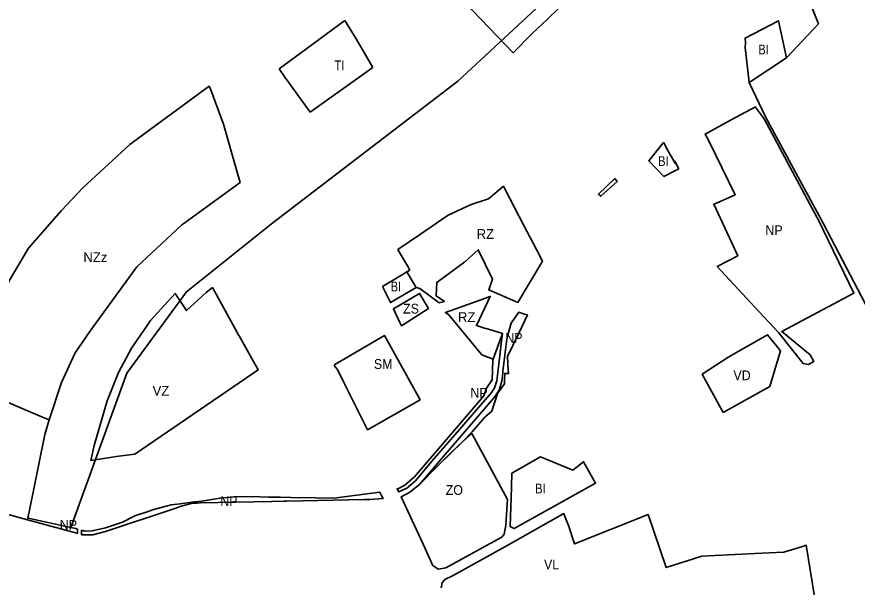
# Model space of a CAD drawing. Extents: x -650276 to -642489, y -1074311 to -1066658.
# Drawn here: x -647227 to -646196, y -1073124 to -1072424 of the extents above; entities that cross this region are included whole.
import ezdxf

# ---------------------------------------------------------------- set-up
doc = ezdxf.new("R2010")
doc.units = 0
doc.header["$LTSCALE"] = 4.8
for name, color, linetype, lineweight in [('18', 7, 'Continuous', 35), ('2', 7, 'Continuous', 35), ('30', 7, 'Continuous', 35), ('34', 7, 'Continuous', 35), ('35', 7, 'Continuous', 35), ('36', 7, 'Continuous', 35), ('41', 7, 'Continuous', 35), ('42', 7, 'Continuous', 35), ('46', 7, 'Continuous', 35), ('48', 7, 'Continuous', 35), ('54', 7, 'Continuous', 35), ('6', 7, 'Continuous', 35)]:
    doc.layers.add(name, color=color, linetype=linetype, lineweight=lineweight)
doc.layers.add('62', color=7, linetype='Continuous')
doc.layers.add('63', color=7, linetype='Continuous')

msp = doc.modelspace()

# ---------------------------------------------------------------- linework, layer by layer
at = {"layer": '18'}
msp.add_lwpolyline([(-646837.81, -1072851.3), (-646836.5, -1072853.76), (-646833.67, -1072857.15), (-646824.89, -1072874.66), (-646796.68, -1072930.92), (-646732.28, -1072894.29), (-646775.85, -1072815.39), (-646834.08, -1072849.15)], close=True, dxfattribs=at)
at = {"layer": '2'}
msp.add_line((-646417.787, -1072612.168), (-646414.77, -1072610.61), dxfattribs=at)
for points in [[(-646333.34, -1072461.67), (-646328.45, -1072504.81), (-646282.47, -1072474.34), (-646292.44, -1072428.89), (-646333.33, -1072450.12), (-646332.68, -1072456.19)], [(-646778.2, -1072755.19), (-646755.1, -1072741.28), (-646748.3, -1072737.01), (-646737.05, -1072756.4), (-646768.74, -1072774.78)], [(-646620.38, -1073015.9), (-646620.71, -1073025.49), (-646621.44, -1073049.79), (-646616.55, -1073052.21), (-646516.7, -1072996.65), (-646531.46, -1072970.12), (-646544.68, -1072980.62), (-646584.23, -1072964.22), (-646619.48, -1072984.34)]]:
    msp.add_lwpolyline(points, close=True, dxfattribs=at)
for points in [[(-646420.36, -1072601.78), (-646427.95, -1072588.07), (-646432.57, -1072579.75), (-646433.36, -1072578.45), (-646451.458, -1072601.008), (-646433.024, -1072620.04), (-646417.787, -1072612.168)], [(-646414.77, -1072610.61), (-646419.11, -1072602.03), (-646419.47, -1072601.31), (-646419.02, -1072604.18), (-646420.36, -1072601.78)]]:
    msp.add_lwpolyline(points, dxfattribs=at)
at = {"layer": '30'}
for points in [[(-646824.42, -1072428.58), (-646878.91, -1072468.54), (-646905.18, -1072487.8)], [(-646867.283, -1072540.984), (-646791.569, -1072487.198), (-646790.354, -1072486.136), (-646810.77, -1072451.09), (-646824.42, -1072428.58)], [(-646905.18, -1072487.8), (-646898.1, -1072498.02), (-646893.64, -1072504.45), (-646867.283, -1072540.984)]]:
    msp.add_lwpolyline(points, dxfattribs=at)
at = {"layer": '34'}
msp.add_lwpolyline([(-646247.76, -1073138.19), (-646258.14, -1073072.71), (-646262.94, -1073074.15), (-646285.77, -1073081.01), (-646312.87, -1073082.4), (-646386.27, -1073086.15), (-646430.02, -1073100.1), (-646452.08, -1073034.96), (-646542.62, -1073071.1), (-646550.01, -1073048.55), (-646552.79, -1073041.53), (-646555.79, -1073033.92), (-646624.69, -1073072.66), (-646691.76, -1073109.71), (-646701.78, -1073114.9), (-646704.98, -1073119), (-646706.23, -1073125.02)], dxfattribs=at)
at = {"layer": '35'}
msp.add_lwpolyline([(-646360.22, -1072909.57), (-646303.02, -1072877.74), (-646289.63, -1072834.04), (-646305.56, -1072814.43), (-646353.25, -1072841.63), (-646385.86, -1072862.59)], close=True, dxfattribs=at)
at = {"layer": '36'}
for points in [[(-646987.154, -1072756.377), (-646995.02, -1072762.45), (-647005.249, -1072771.938), (-647019.06, -1072784.57), (-647032.7, -1072763.68), (-647050.492, -1072782.771)], [(-646954.7, -1072815.232), (-646957.105, -1072810.92), (-646987.154, -1072756.377)], [(-647050.492, -1072782.771), (-647063.04, -1072796.74), (-647067.22, -1072802.77), (-647086.65, -1072830.76), (-647102.38, -1072860.7), (-647116.33, -1072895.3)], [(-647136.39, -1072968.63), (-647110.32, -1072964.56), (-647107.01, -1072964.04), (-647105.4, -1072963.84), (-647082.36, -1072960.95), (-646931.1, -1072857.55), (-646954.51, -1072815.63), (-646954.7, -1072815.232)], [(-647116.33, -1072895.3), (-647132.47, -1072950.4), (-647136.39, -1072968.63)]]:
    msp.add_lwpolyline(points, dxfattribs=at)
at = {"layer": '41'}
msp.add_lwpolyline([(-646756.92, -1072799.26), (-646754.96, -1072803.29), (-646722.072, -1072782.236), (-646732.76, -1072763.81), (-646765, -1072782.52)], close=True, dxfattribs=at)
at = {"layer": '42'}
msp.add_lwpolyline([(-646696.83, -1072385.81), (-646618.158, -1072468.098), (-646594.606, -1072444.422), (-646575.792, -1072426.789), (-646504.244, -1072357.026)], dxfattribs=at)
msp.add_lwpolyline([(-646668.53, -1072935.52), (-646680.07, -1072945.74), (-646710.3, -1072975.31), (-646732.95, -1072998.07), (-646744.92, -1073007.46), (-646755.58, -1073013.43), (-646728.25, -1073071.54), (-646719.09, -1073092.43), (-646716.98, -1073097.26), (-646709.88, -1073101.87), (-646700.42, -1073100.42), (-646650.54, -1073072.96), (-646631.82, -1073062.65), (-646629.15, -1073059.18), (-646626.91, -1073048.17), (-646626.55, -1073041.48), (-646625.01, -1073016.38)], close=True, dxfattribs=at)
at = {"layer": '46'}
msp.add_lwpolyline([(-647284.75, -1072877.79), (-647282.31, -1072878.82), (-647192.718, -1072916.582), (-647187.445, -1072918.804), (-647172.48, -1072872.92), (-647155.72, -1072836.46), (-647136.69, -1072808.98), (-647079.74, -1072731.1), (-647025.04, -1072679.96), (-646953.2, -1072627.45), (-646957.5, -1072612.09), (-646973.68, -1072555.68), (-646989.01, -1072513.62), (-646991.24, -1072509.24), (-647063.38, -1072562.42), (-647088.397, -1072580.865), (-647088.4, -1072580.868), (-647146.21, -1072634.02), (-647172.36, -1072661.69), (-647198.77, -1072691.71), (-647212.92, -1072708.05), (-647236.54, -1072748.09), (-647252.29, -1072783.24), (-647263.58, -1072809.97)], close=True, dxfattribs=at)
at = {"layer": '48'}
msp.add_line((-646779.55, -1073011.68), (-646781.703, -1073007.452), dxfattribs=at)
for points in [[(-646194.19, -1072404.62), (-646254.75, -1072404.25), (-646243.17, -1072432.88), (-646282.47, -1072474.34), (-646328.45, -1072504.81), (-646307.6, -1072547.74), (-646236.97, -1072678.31), (-646171.72, -1072803.51)], [(-646918.156, -1073013.511), (-646928.807, -1073013.313), (-646956.919, -1073012.775), (-646978.077, -1073014.931), (-646997.824, -1073018.092), (-647006.715, -1073019.236), (-647006.15, -1073020.99), (-647001.66, -1073020.72), (-646914.54, -1073019)], [(-646781.703, -1073007.452), (-646809.778, -1073011.019), (-646838.25, -1073014.938), (-646861.07, -1073014.672), (-646890.523, -1073014.073), (-646904.131, -1073013.793), (-646914.796, -1073013.573), (-646918.156, -1073013.511)], [(-646800.44, -1073016.74), (-646793.8, -1073016.61), (-646777.74, -1073015.29), (-646779.55, -1073011.68)], [(-646914.54, -1073019), (-646913.94, -1073018.99), (-646899.22, -1073018.7), (-646895.76, -1073018.63), (-646800.44, -1073016.74)]]:
    msp.add_lwpolyline(points, dxfattribs=at)
for points in [[(-646310.01, -1072549.22), (-646319.56, -1072536.05), (-646320.62, -1072534.6), (-646350.18, -1072550.59), (-646382.41, -1072568.01), (-646377.84, -1072576.29), (-646345.6, -1072642.55), (-646368.51, -1072652.81), (-646371.66, -1072654.2), (-646342.08, -1072717.43), (-646367.72, -1072730.68), (-646321.171, -1072780.535), (-646292.17, -1072811.6), (-646261.97, -1072849.66), (-646255.39, -1072850.83), (-646249.04, -1072847.16), (-646253.56, -1072838.8), (-646288.27, -1072810.22), (-646199.72, -1072763.1), (-646243.32, -1072673.57), (-646245.13, -1072670.2), (-646278.44, -1072608.07)], [(-646493.229, -1072622.74), (-646513.209, -1072641.935), (-646510.28, -1072644.42), (-646490.11, -1072626.15)], [(-646644.059, -1072908.208), (-646637.2, -1072886.57), (-646628.7, -1072874.5), (-646628.58, -1072869.88), (-646628.36, -1072861.71), (-646627.159, -1072861.792), (-646625.96, -1072861.874), (-646625.3, -1072861.919), (-646624.824, -1072861.951), (-646623.67, -1072862.024), (-646623.712, -1072861.37), (-646623.95, -1072857.6), (-646625.02, -1072841.21), (-646618.521, -1072827.719), (-646617.407, -1072825.407), (-646614.07, -1072818.47), (-646600.37, -1072790.04), (-646603.99, -1072788.901), (-646610.86, -1072786.74), (-646620.27, -1072799.95), (-646624.54, -1072814.52), (-646625.91, -1072819.66), (-646630.45, -1072858.93), (-646630.57, -1072859.99), (-646630.76, -1072861.61), (-646631.89, -1072871.33), (-646635.11, -1072882.47), (-646640.96, -1072890.83), (-646684.36, -1072941.43), (-646732.95, -1072998.07), (-646710.3, -1072975.31), (-646693.9, -1072958.84), (-646680.07, -1072945.74), (-646668.09, -1072933.43), (-646652.76, -1072915.66), (-646644.069, -1072908.218), (-646644.061, -1072908.209)], [(-646642.438, -1072844.29), (-646642.939, -1072845.68), (-646643.574, -1072869.57), (-646650.798, -1072879.828), (-646653.846, -1072889.44), (-646692.432, -1072934.135), (-646739.241, -1072988.798), (-646751.061, -1072999.106), (-646758.883, -1073002.885), (-646760.416, -1073003.25), (-646758.44, -1073007.19), (-646748.51, -1073002.74), (-646737.7, -1072993.52), (-646717.7, -1072969.5), (-646689.13, -1072936.62), (-646644.12, -1072884.84), (-646640.92, -1072879.6), (-646637.92, -1072870.91), (-646637.52, -1072867.43), (-646631.85, -1072818.45), (-646631.08, -1072812.68), (-646640.313, -1072838.394), (-646642.404, -1072844.195), (-646642.39, -1072844.2)], [(-647293.317, -1072873.549), (-647293.351, -1072873.533), (-647331.82, -1072854.49), (-647375.92, -1072833.99), (-647387.64, -1072868.69), (-647392.96, -1072918.277), (-647394.87, -1072936.08), (-647388.62, -1072948.03), (-647395.47, -1072993.25), (-647367.45, -1073002.47), (-647353.78, -1073003.1), (-647213.99, -1073041.449), (-647210.396, -1073023.593), (-647207.176, -1073007.598), (-647192.93, -1072936.82), (-647187.445, -1072918.804), (-647192.718, -1072916.582), (-647282.31, -1072878.82), (-647284.75, -1072877.79)], [(-647006.715, -1073019.236), (-647009.402, -1073019.582), (-647026.763, -1073021.811), (-647037.971, -1073023.24), (-647060.677, -1073029.351), (-647064.784, -1073030.747), (-647082.267, -1073036.684), (-647097.466, -1073044.268), (-647118.513, -1073051.327), (-647134.596, -1073054.974), (-647143.312, -1073055.421), (-647147.85, -1073054.204), (-647147.91, -1073059.64), (-647147.43, -1073059.78), (-647147.17, -1073059.97), (-647134.03, -1073059.94), (-647118.27, -1073055.88), (-647033.44, -1073027.43), (-647028.91, -1073025.91), (-647026.54, -1073025.11), (-647013.4, -1073021.42), (-647006.15, -1073020.99)], [(-647152.621, -1073052.925), (-647154.999, -1073052.287), (-647161.068, -1073050.946), (-647161.068, -1073050.946), (-647161.068, -1073050.946), (-647213.218, -1073039.42), (-647213.562, -1073039.322), (-647213.99, -1073041.449), (-647153.44, -1073058.06), (-647152.96, -1073058.19)]]:
    msp.add_lwpolyline(points, close=True, dxfattribs=at)
at = {"layer": '54'}
msp.add_lwpolyline([(-646516, -1072345), (-646685.823, -1072502.987), (-646914.429, -1072678.004), (-647018.969, -1072761.795), (-647092.194, -1072861.614), (-647161.068, -1073050.946)], dxfattribs=at)
at = {"layer": '6'}
for points in [[(-646737.05, -1072756.4), (-646732.5, -1072757.63), (-646708.65, -1072775.02), (-646702.45, -1072773.39), (-646712.46, -1072766.76), (-646711.79, -1072750.02), (-646677.39, -1072724.85), (-646660.89, -1072709.97), (-646643.36, -1072746.04), (-646647.93, -1072759.01), (-646612.11, -1072774.56), (-646581.92, -1072723.91), (-646589.37, -1072709.83), (-646605.23, -1072679.37), (-646627.32, -1072636.95), (-646629.86, -1072632.07), (-646648.27, -1072647.48), (-646669.6, -1072654.53), (-646697.89, -1072667.65)], [(-646697.89, -1072667.65), (-646732.95, -1072691.68), (-646759.491, -1072709.878), (-646757.5, -1072713.3), (-646747.87, -1072729.85), (-646744.94, -1072734.88), (-646748.3, -1072737.01), (-646737.05, -1072756.4)], [(-646653.02, -1072806.07), (-646663.07, -1072803.04), (-646663.07, -1072803.04), (-646646.12, -1072767.32), (-646646.31, -1072767.388), (-646701.12, -1072787.08), (-646697.09, -1072790.03), (-646656.36, -1072839.08)], [(-646656.36, -1072839.08), (-646642.404, -1072844.195), (-646631.08, -1072812.68), (-646643.01, -1072809.08), (-646651.11, -1072806.64), (-646653.02, -1072806.07)]]:
    msp.add_lwpolyline(points, dxfattribs=at)

# ---------------------------------------------------------------- texts
at = {"layer": '62'}
for s, width, p in [('BI', 0.85, (-646317, -1072470.167)), ('TI', 0.85, (-646837.377, -1072489.619)), ('BI', 0.85, (-646440, -1072607.167)), ('NP', 0.95, (-646308.335, -1072692.048)), ('BI', 0.85, (-646768.325, -1072761.133)), ('ZS', 0.95, (-646753.085, -1072788.28)), ('NP', 0.95, (-646627.575, -1072824.064)), ('SM', 0.95, (-646788.938, -1072856.245)), ('VD', 0.95, (-646347.605, -1072870.155)), ('NP', 0.95, (-646670.505, -1072891.594)), ('ZO', 0.95, (-646700.791, -1073010.902)), ('BI', 0.85, (-646590.991, -1073009.043)), ('NP', 0.95, (-646977.505, -1073024.594)), ('NP', 0.95, (-647174.505, -1073053.594)), ('VL', 0.95, (-646580.107, -1073102.218))]:
    msp.add_text(s, height=12, dxfattribs=dict(at, width=width)).set_placement(p)
for s, p in [('RZ', (-646662.725, -1072696.633)), ('NZz', (-647145.58, -1072725.109)), ('RZ', (-646685.725, -1072798.633))]:
    msp.add_text(s, height=12, dxfattribs=at).set_placement(p)
at = {"layer": '63'}
msp.add_text('VZ', height=12, dxfattribs=at).set_placement((-647060.598, -1072889.069))

doc.saveas('drawing.dxf')
